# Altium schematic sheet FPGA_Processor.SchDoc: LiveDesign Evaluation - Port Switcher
size A4; Organization: Altium Limited; Address1: L3, 12a Rodborough Rd; Address2: Frenchs Forest; Address3: NSW; Address4: Australia 2086
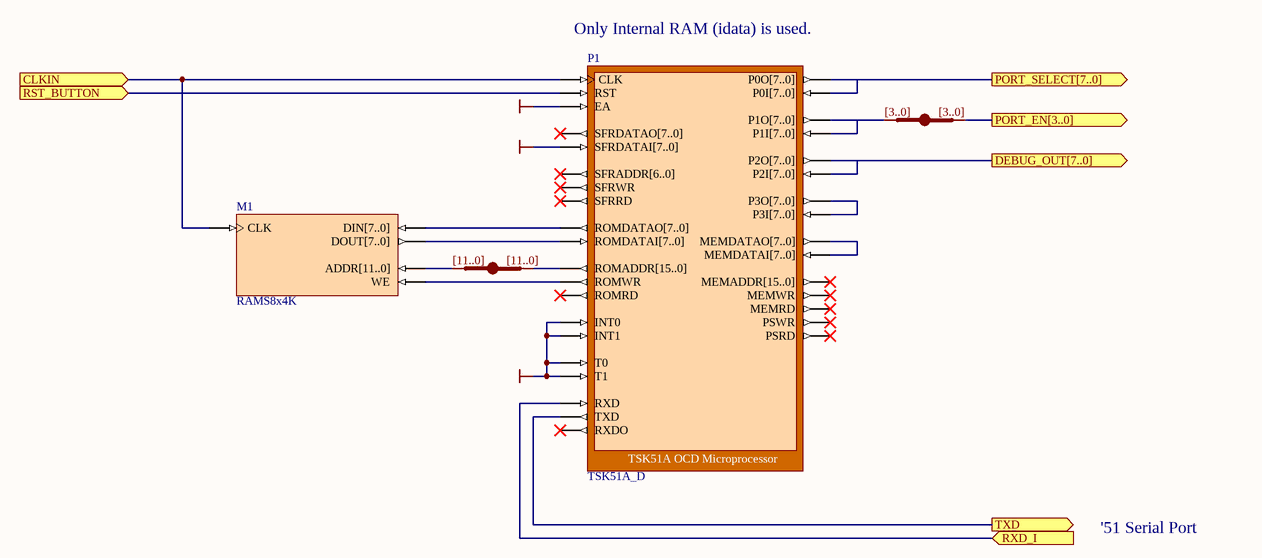
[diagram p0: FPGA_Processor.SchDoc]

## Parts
JB_S10  IndexA: [3..0]  (hidden comment: JB)
JB_S11  IndexA: [11..0]  (hidden comment: JB)
M1  RAMS8x4K
P1  TSK51A_D

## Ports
CLKIN (in), DEBUG_OUT[7..0] (out), PORT_EN[3..0] (out), PORT_SELECT[7..0] (out), RST_BUTTON (in), RXD_I (in), TXD (out)

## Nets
GND: P1.EA P1.INT0 P1.INT1 P1.T0 P1.T1
CLKIN: M1.CLK P1.CLK ; port CLKIN
RST_BUTTON: P1.RST ; port RST_BUTTON
RXD_I: P1.RXD ; port RXD_I
TXD: P1.TXD ; port TXD
NetM1_WE: M1.WE P1.ROMWR

Not connected (* = marked no-connect by the designer): JB_S10 A[0..0] B[0..0]; JB_S11 A[0..0] B[0..0]; M1 ADDR[11..0] DIN[7..0] DOUT[7..0]; P1 MEMADDR[15..0]* MEMDATAI[7..0] MEMDATAO[7..0] MEMRD* MEMWR* P0I[7..0] P0O[7..0] P1I[7..0] P1O[7..0] P2I[7..0] P2O[7..0] P3I[7..0] P3O[7..0] PSRD* PSWR* ROMADDR[15..0] ROMDATAI[7..0] ROMDATAO[7..0] ROMRD* RXDO* SFRADDR[6..0]* SFRDATAI[7..0] SFRDATAO[7..0]* SFRRD* SFRWR*

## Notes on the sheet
- (near P1) Only Internal RAM (idata) is used.
- '51 Serial Port
- Labels drawn without touching a wire or pin: VCCBUS[..]

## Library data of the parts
JB_S10 JB_S11 = JB: System BUS Joiner
M1 = RAMS_8x4K: Single Port RAM; Memory_Depth: 4096; Memory_Type: RAM_SinglePortBlock; Memory_Width: 8; Memory_ClockEdge: Rising; Nexus_Core: Memory_Program; Memory_EnablePin: False
P1 = TSK51A_D: TSK51A OCD Microprocessor; NEXUS_CORE: Processor_OCDS; NEXUS_JTAG_DEVICE: True; NEXUS_JTAG_ORDER: 0; ChildModel1: RAM256x8_TSK51D; ChildCore1: M1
